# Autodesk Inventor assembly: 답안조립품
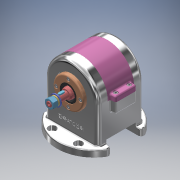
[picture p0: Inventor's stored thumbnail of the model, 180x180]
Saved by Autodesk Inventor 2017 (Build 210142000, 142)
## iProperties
Part Number: 답안조립품
Material: 일반
Document SubType Name: Assembly
Designer: MRC
Author: MRC
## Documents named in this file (21)
- C:\Users\MRC\Desktop\740804V1021\답안조립품.iam
- C:\Users\MRC\Desktop\740804V1021\본체.ipt
- C:\Users\MRC\Desktop\740804V1021\오일레스 부시 20 15.ipt
- C:\Users\MRC\Desktop\740804V1021\부시 커버.ipt
- C:\Users\MRC\Desktop\740804V1021\육각 소켓 머리 볼트 M4x10.ipt
- C:\Users\MRC\Desktop\740804V1021\링크.ipt
- C:\Users\MRC\Desktop\740804V1021\펀치.ipt
- C:\Users\MRC\Desktop\740804V1021\핀.ipt
- C:\Users\MRC\Desktop\740804V1021\E형 멈춤링 10-8.ipt
- C:\Users\MRC\Desktop\740804V1021\깊은 홈 볼 베어링 6904.ipt
- C:\Users\MRC\Desktop\740804V1021\칼라.ipt
- C:\Users\MRC\Desktop\740804V1021\편심축.ipt
- C:\Users\MRC\Desktop\740804V1021\뒷커버.ipt
- C:\Users\MRC\Desktop\740804V1021\오일실 20 32 5.ipt
- C:\Users\MRC\Desktop\740804V1021\앞커버.ipt
- C:\Users\MRC\Desktop\740804V1021\평행키 5x5x12.ipt
- C:\Users\MRC\Desktop\740804V1021\평와셔 M10.ipt
- C:\Users\MRC\Desktop\740804V1021\스퍼 기어.ipt
- C:\Users\MRC\Desktop\740804V1021\스프링 와셔 M10.ipt
- C:\Users\MRC\Desktop\740804V1021\육각 너트 M10x1.ipt
- C:\Users\MRC\Desktop\740804V1021\윗커버.ipt
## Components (2 placed, 2 different names)
1. 핀:1
2. E형 멈춤링 10-8:1
